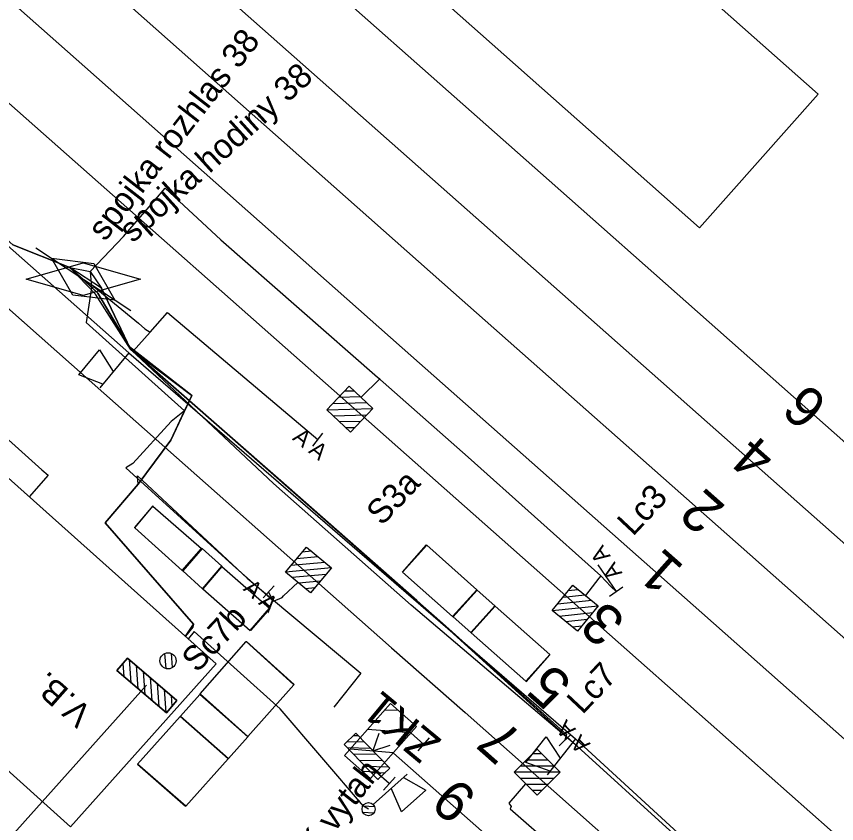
# Model space of a CAD drawing. Extents: x -496570 to -495506, y -1089156 to -1088046.
# Drawn here: x -496405.5 to -496355.2, y -1088285 to -1088235.4 of the extents above; entities that cross this region are included whole.
import ezdxf

# ---------------------------------------------------------------- set-up
doc = ezdxf.new("R2010")
doc.units = 0
for name, color, linetype in [('14', 7, 'Continuous'), ('15', 7, 'Continuous'), ('19', 7, 'Continuous'), ('20', 7, 'Continuous'), ('35', 7, 'Continuous'), ('39', 7, 'Continuous'), ('54', 7, 'Continuous'), ('PŘÍSTUPOVÉ_CESTY', 7, 'Continuous'), ('PŮVODNÍ_NÁVRH', 7, 'Continuous'), ('SEE', 7, 'Continuous')]:
    doc.layers.add(name, color=color, linetype=linetype)

msp = doc.modelspace()

# ---------------------------------------------------------------- linework, layer by layer
at = {"layer": '14'}
for points in [[(-496500.326, -1088150.883), (-496478.319, -1088170.391), (-496459.205, -1088187.309), (-496440.603, -1088203.768), (-496419.398, -1088222.532), (-496401.337, -1088238.524), (-496381.863, -1088255.763), (-496363.496, -1088272.022), (-496344.908, -1088288.479), (-496325.602, -1088305.577), (-496305.115, -1088323.698), (-496285.279, -1088341.274), (-496267.778, -1088356.78), (-496248.642, -1088373.733), (-496220.391, -1088398.759), (-496201.351, -1088415.62), (-496182.974, -1088431.889), (-496164.259, -1088448.462), (-496145.687, -1088464.902), (-496132.984, -1088476.226), (-496115.09, -1088492.058), (-496092.682, -1088511.89), (-496073.961, -1088528.378)], [(-496111.45, -1088501.61), (-496112.796, -1088500.414), (-496116.847, -1088496.777), (-496137.726, -1088478.277), (-496158.004, -1088460.314), (-496179.39, -1088441.364), (-496198.571, -1088424.361), (-496223.52, -1088402.267), (-496247.329, -1088381.198), (-496269.626, -1088361.454), (-496288.304, -1088344.927), (-496319.947, -1088316.905), (-496344.485, -1088295.207), (-496348.139, -1088291.966), (-496366.841, -1088275.405), (-496385.169, -1088259.187), (-496404.395, -1088242.153), (-496422.154, -1088226.434), (-496443.818, -1088207.26), (-496462.548, -1088190.678), (-496481.576, -1088173.849), (-496503.417, -1088154.088)], [(-496036.118, -1088555.5), (-496048.975, -1088544.1), (-496066.196, -1088528.906), (-496086.152, -1088511.349), (-496104.929, -1088494.746), (-496123.588, -1088478.229), (-496142.293, -1088461.701), (-496160.965, -1088445.175), (-496179.891, -1088428.396), (-496198.214, -1088412.189), (-496217.292, -1088395.311), (-496245.811, -1088370.064), (-496264.918, -1088353.145), (-496281.988, -1088338.018), (-496302.247, -1088320.079), (-496322.57, -1088302.076), (-496341.966, -1088284.907), (-496360.552, -1088268.447), (-496378.713, -1088252.378), (-496398.4, -1088234.928), (-496416.447, -1088218.945), (-496437.668, -1088200.162), (-496456.103, -1088183.845), (-496474.042, -1088168.071)], [(-496082.486, -1088502.043), (-496098.63, -1088487.696), (-496117.358, -1088471.138), (-496136.056, -1088454.602), (-496154.785, -1088438.063), (-496173.551, -1088421.521), (-496192.303, -1088405.013), (-496211.05, -1088388.494), (-496229.814, -1088371.969), (-496241.71, -1088361.483), (-496259.312, -1088345.98), (-496335.952, -1088278.18), (-496354.664, -1088261.608), (-496372.853, -1088245.502), (-496392.083, -1088228.459), (-496410.817, -1088211.882), (-496431.795, -1088193.31), (-496448.334, -1088178.663)], [(-496465.102, -1088201.03), (-496456.086, -1088209.031), (-496439.8, -1088223.453), (-496418.031, -1088242.716), (-496400.164, -1088258.552), (-496382.525, -1088274.174), (-496378.001, -1088278.141), (-496364.605, -1088290.03), (-496358.266, -1088295.605), (-496338.75, -1088312.899), (-496318.462, -1088330.866), (-496297.237, -1088349.647), (-496278.02, -1088366.672), (-496252.626, -1088389.158), (-496233.92, -1088405.779), (-496222.755, -1088415.674), (-496210.969, -1088426.126), (-496208.778, -1088428.033)], [(-496419.776, -1088210.17), (-496413.73, -1088215.561), (-496395.384, -1088231.799), (-496375.938, -1088249.024), (-496357.661, -1088265.193), (-496339.088, -1088281.642), (-496320.817, -1088297.785), (-496278.447, -1088335.251), (-496262.212, -1088349.594), (-496242.734, -1088366.795), (-496214.147, -1088392.048), (-496195.339, -1088408.643), (-496176.8, -1088425.002), (-496157.997, -1088441.59), (-496139.148, -1088458.239), (-496120.509, -1088474.69), (-496101.775, -1088491.246), (-496088.913, -1088502.664), (-496081.326, -1088509.353), (-496072.768, -1088516.905)], [(-496238.055, -1088408.352), (-496252.739, -1088395.349), (-496269.088, -1088380.829), (-496284.933, -1088366.798), (-496289.774, -1088362.518), (-496304.914, -1088349.103), (-496331.751, -1088325.354), (-496382.404, -1088280.635)]]:
    msp.add_lwpolyline(points, dxfattribs=at)
at = {"layer": '15'}
for p, q in [((-496385.397, -1088258.408), (-496384.819, -1088258.393)), ((-496386.127, -1088259.178), (-496384.049, -1088259.124)), ((-496385.762, -1088258.793), (-496384.434, -1088258.758)), ((-496386.492, -1088259.562), (-496383.665, -1088259.488)), ((-496386.108, -1088259.927), (-496384.03, -1088259.873)), ((-496385.723, -1088260.293), (-496384.395, -1088260.258)), ((-496385.338, -1088260.657), (-496384.76, -1088260.642)), ((-496387.022, -1088268.588), (-496388.345, -1088268.704)), ((-496387.428, -1088268.248), (-496388.004, -1088268.298)), ((-496386.615, -1088268.929), (-496388.686, -1088269.111)), ((-496386.209, -1088269.27), (-496389.026, -1088269.518)), ((-496386.549, -1088269.676), (-496388.62, -1088269.858)), ((-496386.89, -1088270.083), (-496388.213, -1088270.199)), ((-496387.231, -1088270.489), (-496387.807, -1088270.54)), ((-496371.665, -1088270.65), (-496371.09, -1088270.589)), ((-496371.998, -1088271.062), (-496370.677, -1088270.922)), ((-496372.665, -1088271.888), (-496369.852, -1088271.588)), ((-496372.332, -1088271.475), (-496370.264, -1088271.255)), ((-496372.252, -1088272.221), (-496370.185, -1088272.001)), ((-496371.839, -1088272.554), (-496370.519, -1088272.414)), ((-496371.427, -1088272.887), (-496370.852, -1088272.826)), ((-496373.304, -1088280.678), (-496373.882, -1088280.678)), ((-496372.929, -1088281.053), (-496374.257, -1088281.053)), ((-496372.553, -1088281.428), (-496374.632, -1088281.428)), ((-496372.179, -1088281.803), (-496375.007, -1088281.803)), ((-496372.553, -1088282.178), (-496374.632, -1088282.178)), ((-496372.929, -1088282.553), (-496374.257, -1088282.553)), ((-496373.304, -1088282.928), (-496373.882, -1088282.928))]:
    msp.add_line(p, q, dxfattribs=at)
for points in [[(-496385.115, -1088258.112), (-496383.665, -1088259.488), (-496385.042, -1088260.939), (-496386.492, -1088259.562)], [(-496385.115, -1088258.112), (-496383.665, -1088259.488), (-496385.042, -1088260.939), (-496386.492, -1088259.562)], [(-496387.494, -1088270.802), (-496389.026, -1088269.518), (-496387.741, -1088267.985), (-496386.209, -1088269.27)], [(-496387.494, -1088270.802), (-496389.026, -1088269.518), (-496387.741, -1088267.985), (-496386.209, -1088269.27)], [(-496371.408, -1088270.332), (-496369.852, -1088271.588), (-496371.109, -1088273.144), (-496372.665, -1088271.888)], [(-496371.408, -1088270.332), (-496369.852, -1088271.588), (-496371.109, -1088273.144), (-496372.665, -1088271.888)], [(-496373.593, -1088283.217), (-496375.007, -1088281.803), (-496373.593, -1088280.389), (-496372.179, -1088281.803)], [(-496373.593, -1088283.217), (-496375.007, -1088281.803), (-496373.593, -1088280.389), (-496372.179, -1088281.803)]]:
    msp.add_lwpolyline(points, close=True, dxfattribs=at)
for points in [[(-496385.115, -1088258.112), (-496383.665, -1088259.488), (-496385.042, -1088260.939), (-496386.492, -1088259.562), (-496385.115, -1088258.112)], [(-496385.115, -1088258.112), (-496383.665, -1088259.488), (-496385.042, -1088260.939), (-496386.492, -1088259.562), (-496385.115, -1088258.112)], [(-496387.494, -1088270.802), (-496389.026, -1088269.518), (-496387.741, -1088267.985), (-496386.209, -1088269.27), (-496387.494, -1088270.802)], [(-496387.494, -1088270.802), (-496389.026, -1088269.518), (-496387.741, -1088267.985), (-496386.209, -1088269.27), (-496387.494, -1088270.802)], [(-496371.408, -1088270.332), (-496369.852, -1088271.588), (-496371.109, -1088273.144), (-496372.665, -1088271.888), (-496371.408, -1088270.332)], [(-496371.408, -1088270.332), (-496369.852, -1088271.588), (-496371.109, -1088273.144), (-496372.665, -1088271.888), (-496371.408, -1088270.332)], [(-496373.593, -1088283.217), (-496375.007, -1088281.803), (-496373.593, -1088280.389), (-496372.179, -1088281.803), (-496373.593, -1088283.217)], [(-496373.593, -1088283.217), (-496375.007, -1088281.803), (-496373.593, -1088280.389), (-496372.179, -1088281.803), (-496373.593, -1088283.217)]]:
    msp.add_lwpolyline(points, dxfattribs=at)
at = {"layer": '19'}
for p, q in [((-496396.435, -1088274.518), (-496396.363, -1088275.437)), ((-496396.035, -1088274.512), (-496395.967, -1088275.386)), ((-496398.72, -1088274.797), (-496399.369, -1088275.556)), ((-496399, -1088275.125), (-496398.937, -1088275.925)), ((-496395.679, -1088277.396), (-496398.72, -1088274.797)), ((-496398.617, -1088274.883), (-496398.507, -1088276.293)), ((-496399.369, -1088275.556), (-496396.328, -1088278.155)), ((-496399.368, -1088275.554), (-496399.368, -1088275.557)), ((-496398.188, -1088275.25), (-496398.078, -1088276.66)), ((-496397.759, -1088275.618), (-496397.648, -1088277.027)), ((-496397.329, -1088275.985), (-496397.218, -1088277.395)), ((-496452.007, -1088337.444), (-496397.557, -1088276.455)), ((-496396.898, -1088276.352), (-496396.788, -1088277.763)), ((-496396.468, -1088276.719), (-496396.357, -1088278.13)), ((-496396.038, -1088277.088), (-496395.986, -1088277.754)), ((-496396.328, -1088278.155), (-496395.679, -1088277.396))]:
    msp.add_line(p, q, dxfattribs=at)
msp.add_lwpolyline([(-496395.679, -1088277.396), (-496396.328, -1088278.155), (-496399.369, -1088275.556), (-496398.72, -1088274.797)], close=True, dxfattribs=at)
msp.add_circle((-496396.226, -1088274.964), 0.495, dxfattribs=at)
msp.add_circle((-496396.226, -1088274.964), 0.495, dxfattribs=at)
at = {"layer": '20'}
for p, q in [((-496387.352, -1088261.791), (-496386.728, -1088261.009)), ((-496369.878, -1088269.083), (-496368.75, -1088270.71)), ((-496390.394, -1088271.102), (-496389.726, -1088270.358)), ((-496369.161, -1088270.995), (-496368.339, -1088270.425)), ((-496371.534, -1088279.489), (-496372.246, -1088280.191))]:
    msp.add_line(p, q, dxfattribs=at)
at = {"layer": '35'}
for p, q in [((-496385.411, -1088280.775), (-496382.585, -1088277.579)), ((-496382.585, -1088277.579), (-496380.987, -1088278.992)), ((-496382.938, -1088277.978), (-496382.106, -1088278.003)), ((-496381.34, -1088279.391), (-496383.998, -1088279.177)), ((-496383.813, -1088282.188), (-496380.987, -1088278.992)), ((-496381.34, -1088279.391), (-496380.542, -1088280.097)), ((-496380.895, -1088280.498), (-496380.189, -1088279.698)), ((-496385.058, -1088280.376), (-496382.4, -1088280.59)), ((-496383.813, -1088282.188), (-496385.411, -1088280.775)), ((-496383.46, -1088281.789), (-496384.292, -1088281.764)), ((-496382.661, -1088282.495), (-496383.46, -1088281.789)), ((-496383.46, -1088281.789), (-496383.46, -1088281.789)), ((-496383.014, -1088282.894), (-496382.308, -1088282.095))]:
    msp.add_line(p, q, dxfattribs=at)
at = {"layer": '39'}
for p, q in [((-496397.165, -1088265.462), (-496398.284, -1088266.796)), ((-496398.268, -1088266.812), (-496397.156, -1088265.47)), ((-496397.165, -1088265.462), (-496397.156, -1088265.47)), ((-496397.156, -1088265.47), (-496394.172, -1088268.066)), ((-496398.284, -1088266.796), (-496398.268, -1088266.812)), ((-496398.268, -1088266.812), (-496395.35, -1088269.419)), ((-496395.35, -1088269.419), (-496394.172, -1088268.066)), ((-496394.141, -1088268.083), (-496395.321, -1088269.454)), ((-496394.172, -1088268.066), (-496394.141, -1088268.083)), ((-496394.141, -1088268.083), (-496392.935, -1088269.161)), ((-496381.851, -1088269.52), (-496380.371, -1088267.857)), ((-496381.841, -1088269.533), (-496380.35, -1088267.873)), ((-496380.371, -1088267.857), (-496380.35, -1088267.873)), ((-496380.35, -1088267.873), (-496377.29, -1088270.619)), ((-496394.115, -1088270.54), (-496392.935, -1088269.161)), ((-496392.919, -1088269.173), (-496394.098, -1088270.548)), ((-496392.935, -1088269.161), (-496392.919, -1088269.173)), ((-496392.919, -1088269.173), (-496390, -1088271.745)), ((-496395.35, -1088269.419), (-496395.321, -1088269.454)), ((-496395.321, -1088269.454), (-496394.115, -1088270.54)), ((-496381.851, -1088269.52), (-496381.841, -1088269.533)), ((-496378.777, -1088272.247), (-496381.841, -1088269.533)), ((-496394.098, -1088270.548), (-496394.115, -1088270.54)), ((-496394.098, -1088270.548), (-496391.193, -1088273.099)), ((-496377.29, -1088270.619), (-496378.777, -1088272.247)), ((-496378.751, -1088272.272), (-496377.279, -1088270.63)), ((-496377.29, -1088270.619), (-496377.279, -1088270.63)), ((-496377.279, -1088270.63), (-496376.182, -1088271.603)), ((-496376.182, -1088271.603), (-496377.65, -1088273.239)), ((-496377.642, -1088273.247), (-496376.167, -1088271.614)), ((-496376.182, -1088271.603), (-496376.167, -1088271.614)), ((-496372.824, -1088274.581), (-496376.167, -1088271.614)), ((-496391.193, -1088273.099), (-496390, -1088271.745)), ((-496389.987, -1088271.762), (-496391.175, -1088273.108)), ((-496389.987, -1088271.762), (-496390, -1088271.745)), ((-496378.777, -1088272.247), (-496378.751, -1088272.272)), ((-496377.65, -1088273.239), (-496378.751, -1088272.272)), ((-496391.175, -1088273.108), (-496391.193, -1088273.099)), ((-496377.642, -1088273.247), (-496377.65, -1088273.239)), ((-496377.642, -1088273.247), (-496374.278, -1088276.215)), ((-496394.262, -1088276.997), (-496391.432, -1088273.789)), ((-496391.432, -1088273.789), (-496391.419, -1088273.772)), ((-496391.432, -1088273.789), (-496388.51, -1088276.437)), ((-496388.498, -1088276.426), (-496391.419, -1088273.772)), ((-496372.824, -1088274.581), (-496374.278, -1088276.215)), ((-496374.256, -1088276.233), (-496372.814, -1088274.592)), ((-496372.814, -1088274.592), (-496372.824, -1088274.581)), ((-496374.278, -1088276.215), (-496374.256, -1088276.233)), ((-496391.327, -1088279.616), (-496388.51, -1088276.437)), ((-496388.498, -1088276.426), (-496388.51, -1088276.437)), ((-496395.467, -1088278.361), (-496394.286, -1088277.024)), ((-496394.262, -1088276.997), (-496394.286, -1088277.024)), ((-496394.286, -1088277.024), (-496391.34, -1088279.629)), ((-496391.327, -1088279.616), (-496394.262, -1088276.997)), ((-496398.096, -1088281.306), (-496395.479, -1088278.377)), ((-496395.479, -1088278.377), (-496395.467, -1088278.361)), ((-496395.479, -1088278.377), (-496392.547, -1088280.986)), ((-496392.524, -1088280.963), (-496395.467, -1088278.361)), ((-496392.524, -1088280.963), (-496391.34, -1088279.629)), ((-496391.327, -1088279.616), (-496391.34, -1088279.629)), ((-496392.547, -1088280.986), (-496395.145, -1088283.888)), ((-496392.547, -1088280.986), (-496392.524, -1088280.963)), ((-496398.096, -1088281.306), (-496398.09, -1088281.299)), ((-496395.145, -1088283.888), (-496398.096, -1088281.306)), ((-496398.09, -1088281.299), (-496395.149, -1088283.894)), ((-496395.145, -1088283.888), (-496395.149, -1088283.894))]:
    msp.add_line(p, q, dxfattribs=at)
for points in [[(-496363.629, -1088248.408), (-496376.352, -1088237.135), (-496414.885, -1088202.994), (-496414.205, -1088202.221), (-496437.685, -1088181.558), (-496438.32, -1088182.278), (-496448.933, -1088172.927), (-496441.26, -1088164.27), (-496430.704, -1088173.66), (-496431.375, -1088174.415), (-496421.615, -1088183.225), (-496407.949, -1088195.197), (-496407.6, -1088194.803), (-496356.36, -1088240.202), (-496363.631, -1088248.407)], [(-496502.59, -1088194.713), (-496494.473, -1088185.623), (-496475.87, -1088202.334), (-496475.576, -1088202.006), (-496461.433, -1088214.674), (-496461.12, -1088214.323), (-496443.936, -1088229.62), (-496444.242, -1088229.964), (-496439.802, -1088233.986), (-496432.416, -1088240.415), (-496430.509, -1088242.081), (-496430.212, -1088241.744), (-496412.498, -1088257.374), (-496412.798, -1088257.709), (-496393.266, -1088275.145), (-496402.213, -1088285.146), (-496502.59, -1088194.713)], [(-496410.272, -1088259.964), (-496409.089, -1088258.638), (-496403.957, -1088263.241), (-496403.577, -1088263.582), (-496404.749, -1088264.895)]]:
    msp.add_lwpolyline(points, dxfattribs=at)
at = {"layer": '54'}
for p, q in [((-496404.337, -1088249.626), (-496398.511, -1088253.476)), ((-496403.365, -1088250.268), (-496400.782, -1088250.58)), ((-496402.066, -1088252.522), (-496403.365, -1088250.268)), ((-496400.782, -1088250.58), (-496399.483, -1088252.834)), ((-496399.483, -1088252.834), (-496402.066, -1088252.522)), ((-496389.75, -1088271.3), (-496390.06, -1088270.73))]:
    msp.add_line(p, q, dxfattribs=at)
for points in [[(-496365.46, -1088285.379), (-496371.11, -1088280.23), (-496381.32, -1088271.56), (-496389.75, -1088264.08), (-496398.53, -1088255.84), (-496400.67, -1088252.47), (-496402.25, -1088250.83), (-496405.75, -1088249.45), (-496417.32, -1088239.24), (-496433.49, -1088225.14), (-496450.41, -1088209.86), (-496452.14, -1088207), (-496453.98, -1088204.66), (-496461.089, -1088211.177), (-496461.775, -1088212.207), (-496462.862, -1088213.231)], [(-496452.93, -1088205.3), (-496452.14, -1088207), (-496450.41, -1088209.86), (-496433.49, -1088225.14), (-496417.32, -1088239.24), (-496405.75, -1088249.45), (-496402.25, -1088250.83), (-496401, -1088251.09), (-496400.31, -1088252.1), (-496398.53, -1088255.84), (-496389.47, -1088263.78), (-496380.97, -1088271.27), (-496371.11, -1088280.23), (-496365.46, -1088285.379)], [(-496433.49, -1088225.14), (-496433.04, -1088225.62), (-496416.56, -1088240.21), (-496398.63, -1088256.07), (-496371.25, -1088279.76), (-496353.65, -1088295.93), (-496335.7, -1088311.84), (-496319.23, -1088326.41), (-496317.95, -1088325.09), (-496317.88, -1088325.11), (-496309.26, -1088332.67), (-496302.22, -1088338.89), (-496294.56, -1088345.71), (-496287.4, -1088352.05), (-496279.7, -1088358.86), (-496274.1, -1088363.82), (-496264.77, -1088372.06), (-496257.24, -1088378.7), (-496256.98, -1088378.95)], [(-496401, -1088251.09), (-496398.96, -1088248.94), (-496397, -1088246.66), (-496396.4, -1088245.97), (-496392.99, -1088249.14), (-496383.38, -1088257.56), (-496377.82, -1088262.47), (-496369.69, -1088269.76), (-496369.08, -1088270.41), (-496368.75, -1088270.71)], [(-496401, -1088251.09), (-496400.92, -1088252.09), (-496401.24, -1088254.2), (-496395.21, -1088259.62), (-496396.04, -1088260.29), (-496398.38, -1088262.85), (-496398.82, -1088263.13), (-496392.25, -1088269.09), (-496389.75, -1088271.3), (-496389.23, -1088271.08), (-496389.14, -1088270.98), (-496388.26, -1088270.16)], [(-496400.92, -1088252.09), (-496400.76, -1088252.02), (-496398.03, -1088254.25), (-496397.64, -1088254.59), (-496397.32, -1088254.8), (-496396.26, -1088253.6), (-496387.05, -1088261.39)], [(-496397.32, -1088254.8), (-496398.36, -1088255.96), (-496379.4, -1088272.66), (-496371.8, -1088279.49), (-496371.89, -1088279.84)], [(-496395.155, -1088273.459), (-496394.7, -1088272.91), (-496394.66, -1088272.72), (-496400.09, -1088266.5), (-496398.05, -1088264.13), (-496396.05, -1088261.43), (-496395.21, -1088259.62), (-496394.77, -1088258.68), (-496398.59, -1088255.7)], [(-496383.38, -1088257.56), (-496383.24, -1088257.66), (-496384.39, -1088258.8)], [(-496369.69, -1088269.76), (-496369.81, -1088269.89), (-496370.63, -1088270.96)], [(-496383.93, -1088284.07), (-496384.24, -1088283.88), (-496389.35, -1088277.92), (-496394.62, -1088273.17), (-496394.97, -1088273.6)], [(-496374.3, -1088282.51), (-496375.32, -1088283.69), (-496375.18, -1088283.91), (-496375.25, -1088284.05), (-496372.48, -1088286.46), (-496370.86, -1088287.73), (-496370.15, -1088288.97), (-496369.17, -1088289.13), (-496361.14, -1088296.33), (-496350.64, -1088305.1), (-496347.33, -1088307.69), (-496343.9, -1088311.4), (-496343.6, -1088311.12), (-496341.5, -1088308.75), (-496339.9, -1088307.35), (-496338.669, -1088307.53)]]:
    msp.add_lwpolyline(points, dxfattribs=at)
at = {"layer": 'PŘÍSTUPOVÉ_CESTY'}
for p, q in [((-496398.63, -1088256.07), (-496400.417, -1088258.225)), ((-496384.87, -1088279.549), (-496384.562, -1088279.555)), ((-496385.252, -1088279.916), (-496384.195, -1088279.937)), ((-496371.25, -1088279.76), (-496372.97, -1088281.969)), ((-496385.241, -1088280.292), (-496383.827, -1088280.32)), ((-496384.873, -1088280.674), (-496383.459, -1088280.702)), ((-496384.506, -1088281.056), (-496383.092, -1088281.084)), ((-496384.138, -1088281.439), (-496382.724, -1088281.467)), ((-496383.771, -1088281.821), (-496382.922, -1088281.838)), ((-496381.569, -1088281.915), (-496383.648, -1088283.786)), ((-496383.404, -1088282.203), (-496383.305, -1088282.205)), ((-496381.793, -1088282.116), (-496380.418, -1088282.898)), ((-496381.906, -1088284.234), (-496382.537, -1088282.784)), ((-496380.418, -1088282.898), (-496381.906, -1088284.234)), ((-496384.281, -1088284.258), (-496383.601, -1088284.294)), ((-496384.268, -1088283.858), (-496383.574, -1088283.895))]:
    msp.add_line(p, q, dxfattribs=at)
for points in [[(-496400.226, -1088257.995), (-496401.7, -1088257.422), (-496400.423, -1088255.882), (-496399.587, -1088257.225)], [(-496384.713, -1088279.398), (-496382.634, -1088281.561), (-496383.355, -1088282.254), (-496385.434, -1088280.091), (-496384.713, -1088279.398)], [(-496383.299, -1088279.426), (-496383.674, -1088280.48), (-496382.606, -1088280.147)], [(-496372.786, -1088281.733), (-496374.277, -1088281.206), (-496373.048, -1088279.628), (-496372.172, -1088280.944)]]:
    msp.add_lwpolyline(points, dxfattribs=at)
msp.add_lwpolyline([(-496384.713, -1088279.398), (-496382.634, -1088281.561), (-496383.355, -1088282.254), (-496385.434, -1088280.091)], close=True, dxfattribs=at)
msp.add_circle((-496383.93, -1088284.07), 0.401, dxfattribs=at)
msp.add_circle((-496383.93, -1088284.07), 0.401, dxfattribs=at)
at = {"layer": 'PŮVODNÍ_NÁVRH'}
msp.add_line((-496398.38, -1088262.85), (-496396.04, -1088260.29), dxfattribs=at)
for points in [[(-496338.669, -1088307.53), (-496340.38, -1088305.964), (-496342.857, -1088305.764), (-496354.51, -1088295.443), (-496365.46, -1088285.379), (-496371.11, -1088280.23), (-496380.97, -1088271.27), (-496389.47, -1088263.78), (-496398.53, -1088255.84), (-496400.31, -1088252.1), (-496402.25, -1088250.83), (-496405.75, -1088249.45), (-496417.32, -1088239.24), (-496433.49, -1088225.14), (-496450.41, -1088209.86), (-496452.14, -1088207), (-496452.93, -1088205.3), (-496453.98, -1088204.66)], [(-496401, -1088251.09), (-496398.96, -1088248.94), (-496397, -1088246.66)], [(-496395.155, -1088273.459), (-496394.66, -1088272.72), (-496400.09, -1088266.5), (-496398.05, -1088264.13), (-496396.05, -1088261.43), (-496394.77, -1088258.68), (-496398.59, -1088255.7), (-496400.54, -1088252.4)]]:
    msp.add_lwpolyline(points, dxfattribs=at)
at = {"layer": 'SEE'}
for points in [[(-496462.862, -1088213.231), (-496461.775, -1088212.207), (-496461.089, -1088211.177), (-496453.882, -1088204.587), (-496452.93, -1088205.3), (-496450.41, -1088209.86), (-496405.75, -1088249.45), (-496402.25, -1088250.83), (-496401.424, -1088251.551), (-496400.54, -1088252.4), (-496398.53, -1088255.84), (-496394.77, -1088258.68), (-496396.05, -1088261.43), (-496398.05, -1088264.13), (-496400.09, -1088266.5), (-496394.66, -1088272.72), (-496394.7, -1088272.91), (-496395.155, -1088273.459)], [(-496453.882, -1088204.587), (-496452.93, -1088205.3), (-496452.14, -1088207), (-496450.41, -1088209.86), (-496433.49, -1088225.14), (-496417.32, -1088239.24), (-496405.75, -1088249.45), (-496402.25, -1088250.83), (-496400.54, -1088252.4), (-496398.53, -1088255.84), (-496389.47, -1088263.78), (-496380.97, -1088271.27), (-496371.11, -1088280.23), (-496365.46, -1088285.379)], [(-496453.882, -1088204.587), (-496452.93, -1088205.3), (-496452.14, -1088207), (-496450.41, -1088209.86), (-496433.49, -1088225.14), (-496417.32, -1088239.24), (-496405.75, -1088249.45), (-496402.25, -1088250.83), (-496400.54, -1088252.4), (-496398.53, -1088255.84), (-496389.47, -1088263.78), (-496380.97, -1088271.27), (-496371.11, -1088280.23), (-496365.46, -1088285.379)], [(-496404.924, -1088251.551), (-496401.424, -1088250.551), (-496397.924, -1088251.551), (-496401.424, -1088252.551), (-496404.924, -1088251.551)], [(-496400.54, -1088252.4), (-496398.59, -1088255.7), (-496394.77, -1088258.68), (-496396.05, -1088261.43), (-496398.05, -1088264.13), (-496400.09, -1088266.5), (-496394.66, -1088272.72), (-496394.7, -1088272.91), (-496395.155, -1088273.459)], [(-496398.05, -1088264.13), (-496398.1, -1088263.61), (-496391.37, -1088269.9), (-496384.4, -1088275.73), (-496386.05, -1088277.81)]]:
    msp.add_lwpolyline(points, dxfattribs=at)

# ---------------------------------------------------------------- texts
at = {"layer": '14'}
for s, rotation, p in [('6', 138.4588, (-496355.661, -1088259.088)), ('4', 138.5407, (-496358.815, -1088262.241)), ('2', 138.4806, (-496361.969, -1088265.516)), ('1', 138.4806, (-496364.495, -1088269.219)), ('3', 138.4248, (-496368.06, -1088272.415)), ('5', 138.4774, (-496371.341, -1088276.261)), ('7', 138.4733, (-496374.38, -1088279.593)), ('9', 138.5603, (-496377.17, -1088283.238))]:
    msp.add_text(s, height=2.5, rotation=rotation, dxfattribs=at).set_placement(p)
at = {"layer": '20'}
for s, height, rotation, p in [('  A A', 1, 321.4044, (-496389.23, -1088260.909)), ('S3a', 1.5, 46.7985, (-496383.114, -1088266.734)), ('Lc3', 1.5, 46.7985, (-496367.723, -1088267.37)), ('  A A', 1, 124.7225, (-496367.925, -1088270.191)), ('  A A', 1, 318.0128, (-496392.218, -1088270.111)), ('Sc7b', 1.5, 46.7985, (-496394.435, -1088275.748)), ('Lc7', 1.5, 46.7985, (-496370.813, -1088278.309)), ('  A A', 1, 134.5714, (-496369.774, -1088280.588))]:
    msp.add_text(s, height=height, rotation=rotation, dxfattribs=at).set_placement(p)
at = {"layer": '39'}
msp.add_text('V.B.', height=1.5, rotation=138.4107, dxfattribs=at).set_placement((-496400.802, -1088278.038))
at = {"layer": '54'}
msp.add_text('spojka rozhlas 38', height=1.49999, rotation=52.2176, dxfattribs=at).set_placement((-496400.089, -1088249.285))
at = {"layer": 'PŘÍSTUPOVÉ_CESTY'}
msp.add_text('ZK1', height=2, rotation=140.3457, dxfattribs=at).set_placement((-496379.386, -1088279.851))
at = {"layer": 'SEE'}
for s, rotation, p in [('spojka hodiny 38', 42.216, (-496398.393, -1088249.375)), ('MK vytah', 51.8185, (-496388.24, -1088288.34))]:
    msp.add_text(s, height=1.5, rotation=rotation, dxfattribs=at).set_placement(p)

doc.saveas('drawing.dxf')
